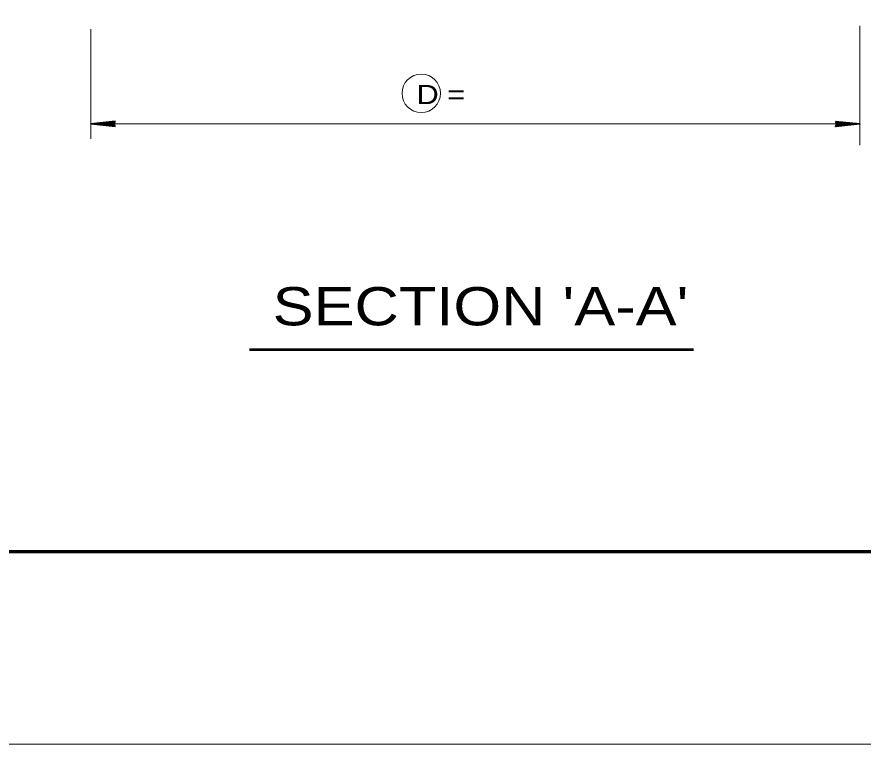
# Model space of a CAD drawing. Extents: x 14.14 to 17.34, y -1.61 to 0.38.
# Drawn here: x 15.4726 to 15.8393, y -1.6047 to -1.2898 of the extents above; entities that cross this region are included whole.
import ezdxf

# ---------------------------------------------------------------- set-up
doc = ezdxf.new("R2010")
doc.units = 0
doc.header["$LTSCALE"] = 0.0033
doc.layers.add('1', color=7, linetype='Continuous', lineweight=40)

msp = doc.modelspace()

# ---------------------------------------------------------------- linework, layer by layer
at = {"layer": '1', "lineweight": 13}
for p, q in [((15.837917, -1.293667), (15.837917, -1.345333)), ((15.504583, -1.295167), (15.504583, -1.342583)), ((15.504667, -1.336167), (15.838, -1.336167)), ((17.339333, -1.60475), (14.142583, -1.60475))]:
    msp.add_line(p, q, dxfattribs=at)
at = {"layer": '1', "lineweight": 35}
for p, q in [((15.515167, -1.336167), (15.504583, -1.336167)), ((15.514917, -1.337), (15.507083, -1.336)), ((15.514917, -1.337), (15.507083, -1.336167)), ((15.514917, -1.337167), (15.507083, -1.33625)), ((15.514917, -1.337167), (15.507083, -1.33625)), ((15.514917, -1.337083), (15.507083, -1.33625)), ((15.514917, -1.335083), (15.507583, -1.335917)), ((15.514917, -1.33525), (15.507583, -1.336)), ((15.514917, -1.335333), (15.507583, -1.336167)), ((15.515, -1.3355), (15.507667, -1.33625)), ((15.827333, -1.336167), (15.837917, -1.336167)), ((15.8275, -1.336833), (15.834833, -1.336083)), ((15.827583, -1.335167), (15.835417, -1.336083)), ((15.827583, -1.335167), (15.835417, -1.336083)), ((15.827583, -1.33525), (15.835417, -1.336083)), ((15.827583, -1.335333), (15.835417, -1.336167)), ((15.827583, -1.335333), (15.835417, -1.336333)), ((15.827583, -1.337), (15.834917, -1.336167)), ((15.827583, -1.337083), (15.834917, -1.336333)), ((15.827583, -1.33725), (15.834917, -1.336417))]:
    msp.add_line(p, q, dxfattribs=at)
at = {"layer": '1', "lineweight": 53}
msp.add_line((15.573417, -1.433917), (15.76575, -1.433917), dxfattribs=at)
at = {"layer": '1', "lineweight": 70}
msp.add_line((14.309333, -1.521417), (17.256, -1.521417), dxfattribs=at)
at = {"layer": '1'}
msp.add_lwpolyline([(14.309333, -1.521417), (16.671, -1.521417), (16.671, -1.196333), (17.256, -1.196333)], dxfattribs=at)
at = {"layer": '1', "lineweight": 35}
for points in [[(15.515167, -1.33725), (15.504583, -1.336167), (15.515167, -1.335), (15.514583, -1.336167)], [(15.514417, -1.33625), (15.50975, -1.336333), (15.50975, -1.33625), (15.510667, -1.33625), (15.514417, -1.336333), (15.511417, -1.336417), (15.514583, -1.3365), (15.512333, -1.336583), (15.514583, -1.336667), (15.511083, -1.336417), (15.506417, -1.33625), (15.507333, -1.336), (15.506083, -1.336), (15.514417, -1.336), (15.512, -1.335833), (15.514583, -1.335833), (15.50925, -1.33625), (15.514583, -1.335583)], [(15.827333, -1.335083), (15.837917, -1.336167), (15.827333, -1.337333), (15.827917, -1.336167)], [(15.828083, -1.336083), (15.83275, -1.336), (15.83275, -1.336083), (15.831833, -1.336083), (15.828083, -1.336), (15.831083, -1.335917), (15.827917, -1.335833), (15.830167, -1.33575), (15.827917, -1.335667), (15.831417, -1.335917), (15.836083, -1.336083), (15.835167, -1.336333), (15.836417, -1.336333), (15.828083, -1.336333), (15.8305, -1.3365), (15.827917, -1.3365), (15.83325, -1.336083), (15.827917, -1.33675)]]:
    msp.add_lwpolyline(points, close=True, dxfattribs=at)
for points in [[(15.514417, -1.33625), (15.514833, -1.337), (15.514583, -1.33675), (15.514417, -1.336417), (15.514167, -1.3365), (15.514333, -1.336833), (15.5145, -1.336083), (15.514667, -1.335583), (15.514917, -1.335167)], [(15.828083, -1.336083), (15.827667, -1.335333), (15.827917, -1.335583), (15.828083, -1.335917), (15.828333, -1.335833), (15.828167, -1.3355), (15.828, -1.33625), (15.827833, -1.33675), (15.827583, -1.337167)]]:
    msp.add_lwpolyline(points, dxfattribs=at)
at = {"layer": '1', "lineweight": 13}
msp.add_circle((15.647833, -1.322917), 0.008333, dxfattribs=at)

# ---------------------------------------------------------------- texts
at = {"layer": '1', "width": 1.2}
for s, height, p in [('D =      ', 0.008334, (15.64575, -1.327583)), ("SECTION 'A-A'", 0.01658, (15.583417, -1.423417))]:
    msp.add_text(s, height=height, dxfattribs=at).set_placement(p)

doc.saveas('drawing.dxf')
